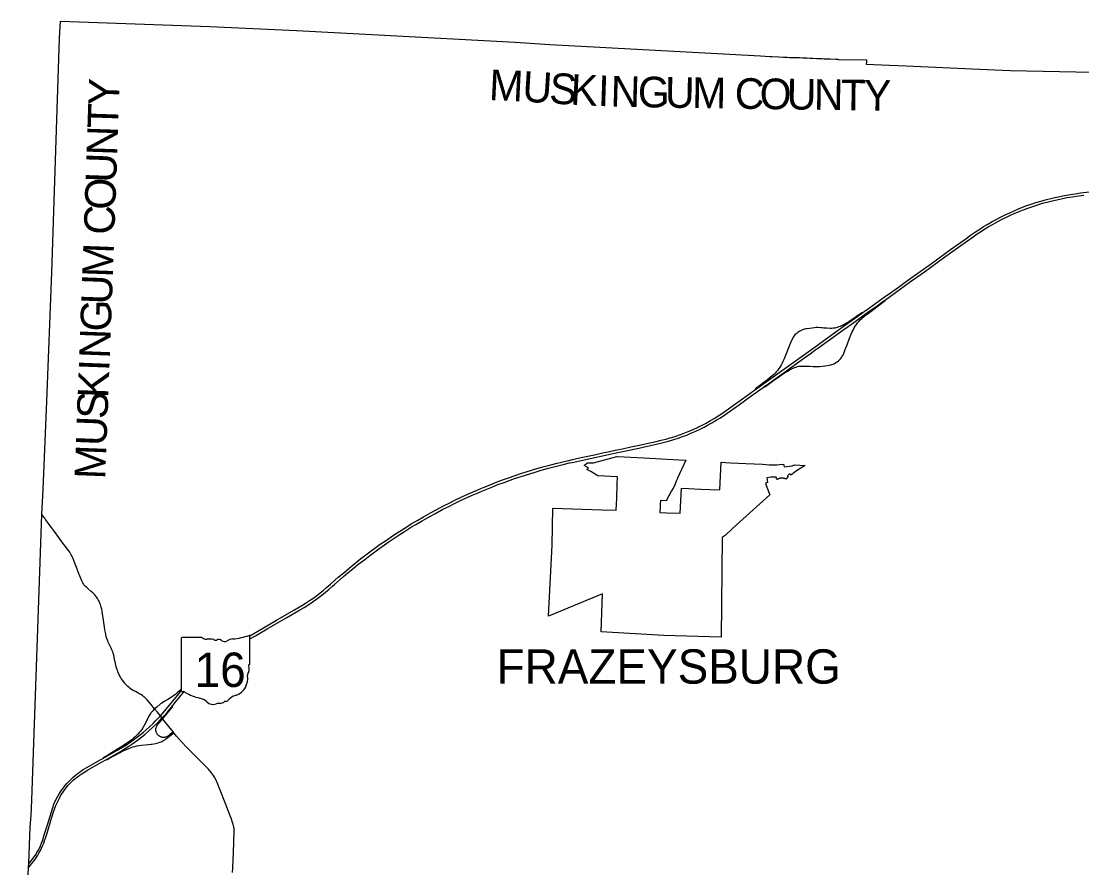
# Model space of a CAD drawing. Extents: x 2015843 to 2287843, y 623733 to 799733.
# Drawn here: x 2069607 to 2104221, y 756520 to 784141 of the extents above; entities that cross this region are included whole.
import ezdxf

# ---------------------------------------------------------------- set-up
doc = ezdxf.new("R2010")
doc.units = 0
for name, color, linetype in [('GM_X_Corporation', 7, 'Continuous'), ('GM_X_Corporation_Text', 7, 'Continuous'), ('GM_X_County', 7, 'Continuous'), ('GM_X_County_Text', 7, 'Continuous'), ('GM_X_State_Location', 7, 'Continuous'), ('GM_X_State_Route', 7, 'Continuous'), ('GM_X_State_Shield', 7, 'Continuous'), ('UT_P_Electric', 7, 'Continuous')]:
    doc.layers.add(name, color=color, linetype=linetype)

msp = doc.modelspace()

# ---------------------------------------------------------------- linework, layer by layer
at = {"layer": 'GM_X_Corporation'}
msp.add_lwpolyline([(2090451, 768115), (2090675, 768106), (2091108, 768088), (2091160, 768909), (2091385, 768898), (2091790, 768878), (2092405, 768847), (2092449, 769752), (2092753, 769737), (2093255, 769712), (2093802, 769685), (2094019, 769672), (2094081, 769669), (2094163, 769666), (2094214, 769665), (2094272, 769668), (2094356, 769677), (2094485, 769685), (2094507, 769605), (2094764, 769634), (2094846, 769670), (2095194, 769643), (2095191, 769641), (2095189, 769640), (2095187, 769639), (2095184, 769637), (2095180, 769635), (2095177, 769633), (2095173, 769631), (2095169, 769629), (2095166, 769627), (2095162, 769625), (2095159, 769624), (2095155, 769622), (2095152, 769620), (2095148, 769618), (2095145, 769616), (2095142, 769614), (2095138, 769612), (2095135, 769610), (2095131, 769608), (2095128, 769606), (2095124, 769604), (2095121, 769602), (2095120, 769601), (2095117, 769600), (2095114, 769598), (2095110, 769596), (2095107, 769594), (2095103, 769592), (2095100, 769590), (2095096, 769588), (2095093, 769586), (2095090, 769584), (2095086, 769582), (2095083, 769580), (2095079, 769578), (2095076, 769576), (2095072, 769574), (2095069, 769572), (2095065, 769570), (2095062, 769568), (2095059, 769565), (2095055, 769563), (2095052, 769561), (2095048, 769559), (2095045, 769557), (2095042, 769555), (2095038, 769553), (2095035, 769551), (2095031, 769549), (2095028, 769547), (2095025, 769544), (2095021, 769542), (2095018, 769540), (2095014, 769538), (2095011, 769536), (2095008, 769534), (2095004, 769532), (2095000, 769529), (2094996, 769527), (2094993, 769525), (2094990, 769523), (2094986, 769520), (2094983, 769518), (2094979, 769516), (2094976, 769514), (2094973, 769512), (2094969, 769510), (2094966, 769508), (2094963, 769505), (2094959, 769503), (2094956, 769501), (2094953, 769499), (2094949, 769497), (2094946, 769495), (2094942, 769492), (2094939, 769490), (2094936, 769488), (2094932, 769486), (2094929, 769484), (2094926, 769481), (2094923, 769479), (2094919, 769477), (2094916, 769475), (2094913, 769472), (2094909, 769470), (2094906, 769468), (2094903, 769466), (2094899, 769463), (2094896, 769461), (2094893, 769459), (2094890, 769456), (2094886, 769454), (2094883, 769452), (2094880, 769449), (2094877, 769447), (2094873, 769445), (2094870, 769443), (2094867, 769440), (2094864, 769438), (2094860, 769435), (2094857, 769433), (2094854, 769431), (2094851, 769428), (2094848, 769426), (2094844, 769424), (2094841, 769421), (2094838, 769419), (2094835, 769416), (2094832, 769414), (2094828, 769412), (2094825, 769409), (2094822, 769407), (2094819, 769404), (2094816, 769402), (2094813, 769399), (2094809, 769397), (2094806, 769394), (2094803, 769392), (2094800, 769389), (2094797, 769387), (2094794, 769384), (2094791, 769382), (2094787, 769379), (2094784, 769377), (2094781, 769374), (2094778, 769372), (2094775, 769369), (2094772, 769367), (2094769, 769364), (2094766, 769362), (2094763, 769359), (2094760, 769357), (2094757, 769354), (2094753, 769352), (2094750, 769349), (2094747, 769346), (2094744, 769344), (2094741, 769341), (2094738, 769339), (2094735, 769336), (2094731, 769333), (2094687, 769377), (2094612, 769312), (2094639, 769281), (2094562, 769203), (2094558, 769205), (2094555, 769207), (2094551, 769208), (2094548, 769210), (2094544, 769212), (2094540, 769213), (2094536, 769214), (2094533, 769216), (2094529, 769217), (2094525, 769218), (2094521, 769220), (2094517, 769221), (2094514, 769222), (2094510, 769223), (2094506, 769224), (2094502, 769225), (2094498, 769226), (2094494, 769226), (2094490, 769227), (2094486, 769228), (2094482, 769229), (2094478, 769229), (2094474, 769230), (2094470, 769230), (2094466, 769231), (2094462, 769231), (2094458, 769231), (2094454, 769232), (2094450, 769232), (2094446, 769232), (2094442, 769232), (2094438, 769232), (2094434, 769232), (2094431, 769232), (2094427, 769232), (2094423, 769232), (2094419, 769232), (2094415, 769232), (2094411, 769231), (2094407, 769231), (2094403, 769231), (2094399, 769230), (2094395, 769230), (2094391, 769229), (2094387, 769228), (2094383, 769228), (2094379, 769227), (2094375, 769226), (2094371, 769225), (2094367, 769224), (2094363, 769223), (2094359, 769222), (2094356, 769221), (2094352, 769220), (2094348, 769219), (2094344, 769218), (2094340, 769216), (2094337, 769215), (2094333, 769214), (2094329, 769212), (2094327, 769212), (2094325, 769211), (2094322, 769209), (2094315, 769207), (2094312, 769205), (2094308, 769203), (2094305, 769201), (2094301, 769199), (2094298, 769198), (2094294, 769196), (2094290, 769194), (2094287, 769192), (2094283, 769191), (2094279, 769189), (2094276, 769187), (2094272, 769186), (2094269, 769184), (2094268, 769184), (2094248, 769267), (2094074, 769267), (2093939, 769244), (2093962, 769085), (2093903, 769072), (2093907, 769031), (2093944, 768940), (2094043, 768692), (2093935, 768594), (2092835, 767601), (2092580, 767365), (2092479, 767294), (2092479, 767294), (2092455, 764039), (2090584, 764096), (2088537, 764215), (2088582, 765461), (2086820, 764727), (2086932, 767051), (2086954, 768249), (2088555, 768201), (2089023, 768183), (2089041, 768582), (2089061, 769039), (2089071, 769274), (2088428, 769311), (2088198, 769446), (2088072, 769514), (2088123, 769568), (2088052, 769606), (2087981, 769644), (2087976, 769648), (2088069, 769725), (2088076, 769726), (2088082, 769728), (2088281, 769735), (2089051, 769936), (2089070, 769940), (2089924, 769893), (2090119, 769882), (2091265, 769819), (2091293, 769818), (2091027, 769228), (2091023, 769218), (2090987, 769133), (2090947, 769039), (2090920, 768978), (2090916, 768968), (2090914, 768965), (2090913, 768961), (2090911, 768958), (2090911, 768956), (2090909, 768952), (2090907, 768948), (2090906, 768945), (2090904, 768942), (2090902, 768938), (2090900, 768935), (2090898, 768930), (2090896, 768927), (2090895, 768924), (2090893, 768921), (2090890, 768916), (2090888, 768912), (2090886, 768908), (2090882, 768903), (2090832, 768814), (2090769, 768701), (2090768, 768700), (2090761, 768687), (2090758, 768684), (2090755, 768678), (2090752, 768673), (2090749, 768669), (2090746, 768664), (2090743, 768659), (2090741, 768655), (2090739, 768652), (2090738, 768650), (2090733, 768642), (2090729, 768636), (2090726, 768631), (2090723, 768625), (2090720, 768620), (2090718, 768615), (2090715, 768611), (2090713, 768606), (2090711, 768601), (2090708, 768596), (2090705, 768591), (2090703, 768587), (2090701, 768582), (2090699, 768578), (2090696, 768572), (2090694, 768567), (2090692, 768562), (2090689, 768557), (2090687, 768553), (2090685, 768547), (2090682, 768540), (2090680, 768535), (2090678, 768531), (2090676, 768526), (2090671, 768514), (2090670, 768510), (2090668, 768506), (2090667, 768503), (2090665, 768498), (2090665, 768496), (2090664, 768494), (2090663, 768491), (2090467, 768500), (2090461, 768368), (2090459, 768300)], close=True, dxfattribs=at)
at = {"layer": 'GM_X_County'}
msp.add_lwpolyline([(2069607, 750462), (2069850, 756543), (2069853, 756656), (2069894, 757841), (2069935, 758229), (2069959, 758723), (2070278, 768051), (2070323, 768867), (2070448, 771746), (2070609, 775946), (2070855, 783589), (2070892, 784141), (2075761, 783968), (2078590, 783843), (2081257, 783694), (2085728, 783453), (2086861, 783383), (2088289, 783309), (2093740, 783008), (2094035, 782985), (2094106, 782985), (2094337, 782976), (2094488, 782969), (2094603, 782966), (2094685, 782962), (2094750, 782959), (2094881, 782955), (2095012, 782953), (2095111, 782950), (2095242, 782945), (2095356, 782939), (2095438, 782934), (2095573, 782928), (2095747, 782920), (2095812, 782918), (2095815, 782918), (2095910, 782915), (2096008, 782912), (2096189, 782906), (2096240, 782904), (2096257, 782902), (2096267, 782900), (2096273, 782897), (2097198, 782879), (2097195, 782802), (2097194, 782787), (2097189, 782758), (2097184, 782735), (2097949, 782707), (2098487, 782682), (2100643, 782587), (2101884, 782528), (2105109, 782463)], dxfattribs=at)
at = {"layer": 'GM_X_State_Route'}
for points in [[(2072992, 762537), (2072988, 762542), (2072947, 762593), (2072908, 762646), (2072874, 762699), (2072838, 762762), (2072809, 762816), (2072775, 762890), (2072756, 762935), (2072739, 762982), (2072719, 763044), (2072698, 763123), (2072683, 763187), (2072674, 763235), (2072667, 763267), (2072645, 763379), (2072626, 763458), (2072608, 763521), (2072592, 763566), (2072567, 763627), (2072540, 763685), (2072496, 763773), (2072475, 763818), (2072449, 763878), (2072431, 763923), (2072404, 764001), (2072385, 764064), (2072370, 764127), (2072357, 764191), (2072340, 764288), (2072324, 764379), (2072302, 764522), (2072279, 764680), (2072261, 764794), (2072246, 764891), (2072234, 764955), (2072219, 765019), (2072206, 765066), (2072190, 765112), (2072173, 765157), (2072146, 765216), (2072124, 765260), (2072099, 765302), (2072072, 765343), (2072043, 765382), (2072010, 765420), (2071977, 765456), (2071942, 765489), (2071893, 765532), (2071794, 765616), (2071745, 765660), (2071710, 765695), (2071688, 765718), (2071664, 765746), (2071643, 765779), (2071621, 765816), (2071588, 765884), (2071481, 766145), (2071424, 766297), (2071394, 766374), (2071328, 766541), (2071290, 766631), (2071269, 766676), (2071240, 766733), (2071215, 766776), (2071189, 766817), (2071123, 766910), (2070938, 767159), (2070840, 767291), (2070694, 767488), (2070597, 767620), (2070518, 767725), (2070440, 767830), (2070401, 767883), (2070373, 767922), (2070354, 767948), (2070324, 767987), (2070279, 768048)], [(2074244, 761355), (2074225, 761379), (2074206, 761404), (2074164, 761456), (2074148, 761476), (2074051, 761597), (2073958, 761710), (2073833, 761861), (2073716, 761998), (2073673, 762043), (2073640, 762075), (2073607, 762102), (2073562, 762136), (2073509, 762170), (2073444, 762207), (2073332, 762266), (2073260, 762306), (2073206, 762339), (2073166, 762368), (2073126, 762398), (2073091, 762429), (2073052, 762466), (2073021, 762502), (2072992, 762537)], [(2075142, 760317), (2075100, 760359), (2075076, 760383), (2074996, 760465), (2074872, 760594), (2074762, 760716), (2074679, 760812), (2074587, 760925), (2074564, 760953), (2074530, 760994), (2074469, 761070), (2074378, 761186), (2074266, 761328), (2074244, 761355)], [(2076532, 756984), (2076548, 757385), (2076557, 757677), (2076558, 757728), (2076555, 757779), (2076552, 757814), (2076548, 757845), (2076539, 757892), (2076527, 757940), (2076507, 758002), (2076469, 758110), (2076352, 758413), (2076303, 758535), (2076058, 759159), (2076022, 759250), (2075990, 759326), (2075955, 759399), (2075916, 759471), (2075883, 759528), (2075854, 759569), (2075815, 759620), (2075777, 759667), (2075751, 759698), (2075720, 759733), (2075284, 760174), (2075239, 760220), (2075146, 760313), (2075142, 760317)], [(2076507, 756363), (2076513, 756522), (2076524, 756801), (2076532, 756984)]]:
    msp.add_lwpolyline(points, dxfattribs=at)
at = {"layer": 'GM_X_State_Shield'}
for p, q in [((2074829, 764001), (2074829, 762300)), ((2075507, 764030), (2074851, 764030)), ((2077070, 763183), (2077070, 764073)), ((2077070, 763183), (2077070, 763183))]:
    msp.add_line(p, q, dxfattribs=at)
for centre, radius, start, end in [((2074855, 764005), 26, 98.1301, 188.1301), ((2075664, 764228), 252, 231.6195, 271.1119), ((2075747, 763075), 904, 80.4867, 94.9883), ((2075953, 764014), 72.7, 219.7921, 297.1024), ((2076059, 763817), 151, 54.4667, 119.1411), ((2076254, 764087), 182, 233.8562, 294.8282), ((2076575, 763511), 478, 97.3462, 120.7689), ((2076272, 766350), 2377, 275.8445, 288.9065), ((2077046, 764076), 25, 351.8621, 97.738), ((2077160, 762810), 169, 136.8065, 186.9296), ((2077065, 763117), 38.6, 107.944, 210.337), ((2076819, 763005), 232, 340.033, 23.6496), ((2077044, 763179), 26.7, 289.6038, 7.7341), ((2076405, 762697), 595, 292.3089, 8.9858), ((2074855, 762296), 26.2, 171.9584, 258.3066), ((2074859, 762470), 200, 267.339, 280.6039), ((2074900, 762202), 72.1, 29.7484, 93.2717), ((2075810, 763730), 1716, 240.4129, 257.1985), ((2075298, 761536), 537, 47.1842, 75.836), ((2075879, 762193), 341, 230.7004, 286.2918), ((2076076, 761605), 280, 85.6951, 111.2099), ((2076101, 762066), 182, 268.777, 315.5493), ((2076265, 761901), 51.1, 65.7517, 132.6484), ((2076243, 762135), 192, 282.8732, 323.2771), ((2076656, 761822), 326, 94.4031, 142.5768)]:
    msp.add_arc(centre, radius, start, end, dxfattribs=at)
at = {"layer": 'UT_P_Electric'}
msp.add_line((2097076, 774636), (2097196, 774722), dxfattribs=at)
for points in [[(2097196, 774722), (2097221, 774740), (2097502, 774940), (2097742, 775111), (2097982, 775283), (2098235, 775464), (2098462, 775627), (2098688, 775790), (2099315, 776239), (2099940, 776689), (2100261, 776917), (2100433, 777042), (2100594, 777156), (2100756, 777268), (2100892, 777359), (2101016, 777438), (2101156, 777523), (2101298, 777605), (2101427, 777675), (2101573, 777751), (2101720, 777823), (2101868, 777893), (2102018, 777959), (2102154, 778017), (2102291, 778071), (2102429, 778123), (2102599, 778182), (2102724, 778223), (2102928, 778285), (2102963, 778295), (2103070, 778325), (2103165, 778350), (2103340, 778392), (2103500, 778427), (2103661, 778459), (2103855, 778492), (2104001, 778514), (2104179, 778537), (2104571, 778580)], [(2097827, 775064), (2097929, 775136), (2098182, 775318), (2098420, 775491), (2098634, 775644), (2098834, 775787), (2099087, 775969), (2099500, 776265), (2099713, 776418), (2099940, 776579), (2100273, 776819), (2100459, 776953), (2100673, 777105), (2100808, 777199), (2100917, 777272), (2101027, 777343), (2101168, 777428), (2101324, 777518), (2101482, 777605), (2101627, 777681), (2101759, 777747), (2101878, 777803), (2102013, 777863), (2102195, 777939), (2102316, 777987), (2102455, 778039), (2102625, 778099), (2102781, 778151), (2102937, 778200), (2103022, 778224), (2103079, 778241), (2103206, 778274), (2103350, 778307), (2103607, 778361), (2103736, 778385), (2103914, 778414), (2104109, 778441), (2104289, 778463)], [(2095568, 772870), (2095643, 772870), (2095675, 772872), (2095919, 772906), (2095984, 772917), (2096032, 772928), (2096064, 772938), (2096110, 772955), (2096154, 772976), (2096197, 773001), (2096238, 773029), (2096276, 773060), (2096312, 773094), (2096345, 773130), (2096375, 773169), (2096394, 773196), (2096419, 773239), (2096442, 773283), (2096462, 773328), (2096503, 773435), (2096573, 773620), (2096644, 773804), (2096693, 773926), (2096726, 774001), (2096755, 774060), (2096795, 774132), (2096829, 774188), (2096866, 774243), (2096905, 774296), (2096947, 774346), (2096991, 774395), (2097038, 774441), (2097086, 774485), (2097150, 774538), (2097214, 774588), (2097476, 774781), (2097716, 774958), (2097753, 774985), (2097803, 775026), (2097815, 775040), (2097827, 775064)], [(2097287, 774680), (2097541, 774860), (2097728, 774994), (2097827, 775064)], [(2079771, 765710), (2079830, 765761), (2079933, 765851), (2080129, 766024), (2080279, 766152), (2080431, 766278), (2080597, 766411), (2080817, 766583), (2080986, 766712), (2081144, 766830), (2081277, 766926), (2081465, 767059), (2081613, 767161), (2081940, 767379), (2082119, 767495), (2082314, 767617), (2082482, 767719), (2082695, 767843), (2082923, 767973), (2083124, 768083), (2083370, 768215), (2083560, 768312), (2083765, 768415), (2083943, 768500), (2084300, 768664), (2084466, 768736), (2084639, 768809), (2084753, 768856), (2084966, 768943), (2085164, 769020), (2085364, 769095), (2085564, 769168), (2085704, 769217), (2086062, 769334), (2086376, 769432), (2086580, 769492), (2086817, 769558), (2086992, 769603), (2087294, 769679), (2087502, 769728), (2087585, 769746), (2087742, 769780), (2088079, 769853), (2088575, 769961), (2088816, 770012), (2089024, 770057), (2089393, 770136), (2089762, 770215), (2090291, 770330), (2090514, 770381), (2090642, 770414), (2090736, 770440), (2090909, 770492), (2091049, 770537), (2091188, 770586), (2091326, 770639), (2091463, 770695), (2091628, 770767), (2091648, 770777), (2091746, 770823), (2091893, 770896), (2092009, 770957), (2092152, 771037), (2092293, 771120), (2092405, 771189), (2092528, 771270), (2092649, 771355), (2092863, 771507), (2093050, 771640), (2093210, 771755), (2093463, 771936), (2093530, 771984), (2093717, 772117), (2093820, 772191), (2093837, 772203), (2094036, 772347), (2094169, 772443), (2094275, 772520), (2094583, 772738), (2094677, 772805), (2094823, 772910), (2095222, 773198), (2095343, 773283), (2095410, 773331), (2095556, 773436), (2095591, 773461), (2096421, 774059), (2096595, 774183), (2096781, 774316), (2096912, 774411), (2097034, 774499), (2097287, 774680)], [(2077067, 764090), (2077517, 764351), (2077941, 764600), (2078509, 764929), (2078764, 765078), (2078890, 765155), (2079014, 765235), (2079122, 765309), (2079242, 765396), (2079359, 765486), (2079462, 765568), (2079574, 765664), (2079696, 765770), (2079723, 765793), (2079956, 765999), (2080131, 766148), (2080307, 766296), (2080497, 766451), (2080638, 766564), (2080859, 766734), (2081029, 766862), (2081188, 766978), (2081322, 767073), (2081524, 767213), (2081755, 767369), (2081961, 767503), (2082155, 767625), (2082336, 767737), (2082548, 767862), (2082732, 767969), (2082961, 768097), (2083148, 768199), (2083366, 768313), (2083570, 768418), (2083717, 768491), (2084014, 768631), (2084208, 768718), (2084508, 768850), (2084605, 768891), (2084719, 768939), (2084917, 769019), (2085146, 769109), (2085345, 769184), (2085515, 769245), (2085731, 769321), (2085918, 769382), (2086263, 769490), (2086435, 769542), (2086672, 769610), (2086893, 769671), (2087100, 769724), (2087195, 769747), (2087371, 769789), (2087476, 769812), (2087594, 769839), (2087883, 769901), (2088315, 769995), (2088491, 770034), (2088635, 770066), (2088763, 770093), (2088988, 770141), (2089228, 770192), (2089501, 770250), (2089886, 770334), (2090126, 770385), (2090287, 770419), (2090447, 770456), (2090542, 770479), (2090653, 770509), (2090779, 770545), (2090843, 770561), (2090906, 770579), (2090985, 770603), (2091062, 770630), (2091154, 770665), (2091373, 770750), (2091456, 770787), (2091539, 770823), (2091680, 770889), (2091710, 770903), (2091784, 770938), (2091872, 770983), (2091959, 771030), (2092102, 771110), (2092243, 771193), (2092355, 771263), (2092464, 771335), (2092612, 771438), (2092812, 771582), (2093145, 771821), (2093505, 772079), (2093544, 772107), (2093772, 772271), (2095595, 773575), (2095849, 773756), (2096195, 774005), (2096435, 774176), (2096622, 774309), (2096836, 774462), (2096913, 774518), (2097076, 774636)], [(2097076, 774636), (2097040, 774625), (2097011, 774609), (2096964, 774575), (2096913, 774539), (2096779, 774445), (2096690, 774382), (2096621, 774337), (2096551, 774295), (2096480, 774255), (2096406, 774218), (2096383, 774207)], [(2095622, 774145), (2095572, 774145), (2095549, 774145), (2095498, 774140), (2095422, 774131), (2095259, 774109), (2095210, 774101), (2095161, 774090), (2095114, 774075), (2095083, 774063), (2095038, 774041), (2094995, 774016), (2094954, 773987), (2094929, 773967), (2094897, 773940), (2094861, 773905)], [(2096383, 774207), (2096332, 774184), (2096286, 774165), (2096239, 774149), (2096192, 774137), (2096160, 774130), (2096111, 774123), (2096062, 774120), (2096013, 774120), (2095898, 774125), (2095803, 774128), (2095747, 774132), (2095703, 774137), (2095622, 774145)], [(2094861, 773905), (2094828, 773869), (2094789, 773813), (2094764, 773765), (2094718, 773646), (2094507, 773130), (2094468, 773040), (2094439, 772981), (2094407, 772923), (2094373, 772867), (2094337, 772813), (2094298, 772760), (2094256, 772709), (2094212, 772661), (2094166, 772614), (2094118, 772569), (2094056, 772516), (2093966, 772445), (2093809, 772326), (2093785, 772308), (2093612, 772178), (2093576, 772150), (2093557, 772128), (2093544, 772107)], [(2093820, 772191), (2093876, 772212), (2093913, 772234), (2094173, 772427), (2094287, 772506), (2094420, 772600), (2094503, 772654), (2094601, 772714), (2094686, 772762), (2094759, 772800), (2094769, 772805)], [(2094769, 772805), (2094803, 772822), (2094848, 772841), (2094895, 772857), (2094942, 772871), (2094990, 772881), (2095038, 772888), (2095087, 772891), (2095153, 772891), (2095349, 772883), (2095449, 772879), (2095568, 772870)], [(2077070, 763986), (2077253, 764092), (2077636, 764314), (2078274, 764685), (2078671, 764917), (2078840, 765017), (2078994, 765112), (2079103, 765184), (2079211, 765259), (2079330, 765346), (2079421, 765415), (2079536, 765508), (2079661, 765613), (2079771, 765710)], [(2069854, 756653), (2069925, 756732), (2069976, 756797), (2070024, 756863), (2070079, 756945), (2070122, 757015), (2070162, 757086), (2070199, 757160), (2070233, 757235), (2070270, 757326), (2070308, 757434), (2070359, 757590), (2070461, 757920), (2070549, 758205), (2070591, 758343), (2070638, 758483), (2070677, 758590), (2070708, 758666), (2070735, 758726), (2070763, 758785), (2070802, 758857), (2070843, 758927), (2070887, 758996), (2070933, 759064), (2070982, 759130), (2071033, 759194), (2071097, 759268), (2071164, 759340), (2071233, 759410), (2071293, 759466), (2071367, 759530), (2071430, 759582), (2071496, 759631), (2071549, 759668), (2071632, 759721), (2071745, 759789), (2072186, 760040), (2072269, 760087), (2072786, 760380), (2072913, 760455), (2073038, 760534), (2073161, 760615), (2073282, 760700), (2073401, 760788), (2073505, 760868), (2073594, 760942), (2073693, 761028), (2073790, 761116), (2073909, 761229), (2073991, 761309), (2074082, 761404), (2074148, 761476), (2074160, 761489), (2074235, 761575), (2074342, 761700), (2074705, 762144), (2074829, 762294)], [(2074829, 762343), (2074775, 762292), (2074701, 762227), (2074638, 762175), (2074586, 762136), (2074532, 762098), (2074477, 762063), (2074392, 762014), (2074292, 761957), (2074237, 761923), (2074196, 761896), (2074156, 761867), (2074028, 761765), (2073958, 761710)], [(2074191, 761388), (2074206, 761404), (2074274, 761479), (2074370, 761591), (2074557, 761818), (2074631, 761907), (2074789, 762096), (2074930, 762267)], [(2073958, 761710), (2073891, 761634), (2073868, 761606), (2073851, 761583), (2073835, 761562), (2073808, 761521), (2073777, 761464), (2073671, 761261), (2073616, 761160), (2073575, 761090), (2073539, 761035), (2073501, 760981), (2073461, 760930), (2073418, 760881), (2073373, 760833), (2073326, 760788), (2073277, 760745), (2073213, 760694), (2073120, 760626), (2073026, 760561), (2072916, 760490), (2072749, 760387), (2072434, 760191), (2072357, 760149), (2072296, 760113), (2072269, 760087)], [(2074564, 760953), (2074488, 760887), (2074451, 760854), (2074412, 760825), (2074385, 760807), (2074355, 760792), (2074340, 760786), (2074324, 760781), (2074309, 760777), (2074292, 760774), (2074276, 760772), (2074260, 760772), (2074243, 760772), (2074227, 760773), (2074211, 760776), (2074195, 760779), (2074179, 760784), (2074164, 760789), (2074148, 760796), (2074134, 760803), (2074120, 760811), (2074106, 760821), (2074093, 760831), (2074081, 760842), (2074069, 760853), (2074059, 760866), (2074049, 760879), (2074040, 760893), (2074032, 760907), (2074024, 760922), (2074013, 760952), (2074009, 760968), (2074003, 761001), (2074002, 761017), (2074003, 761050), (2074005, 761066), (2074013, 761098), (2074018, 761113), (2074031, 761143), (2074047, 761172), (2074065, 761199), (2074096, 761238), (2074128, 761275), (2074207, 761358), (2074225, 761379), (2074262, 761420), (2074317, 761487), (2074500, 761712), (2074520, 761738), (2074542, 761771), (2074550, 761789), (2074557, 761818)], [(2071262, 759334), (2071306, 759375), (2071368, 759430), (2071432, 759481), (2071497, 759530), (2071565, 759577), (2071648, 759630), (2071775, 759706), (2072131, 759910), (2072371, 760047), (2072601, 760177), (2072843, 760316), (2072999, 760407), (2073124, 760485), (2073219, 760549), (2073327, 760624), (2073445, 760712), (2073549, 760792), (2073637, 760865), (2073760, 760973), (2073894, 761094), (2074001, 761196), (2074117, 761311), (2074191, 761388)], [(2073852, 760548), (2073873, 760551), (2073938, 760560), (2073987, 760570), (2074035, 760582), (2074082, 760596), (2074128, 760613), (2074174, 760632), (2074233, 760661), (2074290, 760694), (2074331, 760722), (2074396, 760771), (2074499, 760854), (2074587, 760925)], [(2072371, 760047), (2072411, 760056), (2072469, 760088), (2072677, 760199), (2072832, 760281), (2072935, 760333), (2073039, 760381), (2073115, 760413), (2073176, 760437), (2073255, 760462), (2073318, 760480), (2073382, 760494), (2073447, 760506), (2073529, 760517), (2073758, 760538), (2073852, 760548)], [(2070383, 757444), (2070385, 757448), (2070431, 757588), (2070509, 757839), (2070600, 758137), (2070621, 758203), (2070654, 758309), (2070696, 758434), (2070730, 758526), (2070768, 758617), (2070809, 758707), (2070853, 758795), (2070894, 758866), (2070936, 758936), (2070982, 759005), (2071030, 759071), (2071080, 759136), (2071133, 759199), (2071188, 759260), (2071246, 759319), (2071262, 759334)], [(2069851, 756540), (2069998, 756713), (2070047, 756779), (2070093, 756846), (2070146, 756929), (2070187, 757000), (2070234, 757086), (2070270, 757159), (2070303, 757234), (2070340, 757325), (2070383, 757444)]]:
    msp.add_lwpolyline(points, dxfattribs=at)

# ---------------------------------------------------------------- texts
at = {"layer": 'GM_X_Corporation_Text'}
msp.add_text('FRAZEYSBURG', height=1120, rotation=0, dxfattribs=at).set_placement((2085123, 762527))
at = {"layer": 'GM_X_County_Text'}
for s, rotation, p in [('M', 357.2115, (2084860, 781572)), ('U', 356.4278, (2085942, 781520)), ('S', 356.4112, (2086824, 781464)), ('K', 357.0853, (2087513, 781421)), ('I', 358.1377, (2088417, 781376)), ('N', 358.4214, (2088831, 781362)), ('G', 358.9475, (2089725, 781338)), ('U', 359.1434, (2090613, 781321)), ('M', 359.1871, (2091498, 781308)), ('C', 359.1883, (2092889, 781288)), ('O', 359.1883, (2093702, 781277)), ('Y', 88.0873, (2072791, 781371)), ('U', 359.1877, (2094587, 781264)), ('N', 359.1883, (2095471, 781252)), ('T', 359.1887, (2096355, 781239)), ('Y', 359.1883, (2097103, 781229)), ('T', 88.0873, (2072766, 780625)), ('N', 88.0714, (2072736, 779743)), ('U', 88.0411, (2072706, 778860)), ('O', 88.001, (2072675, 777977)), ('C', 87.9537, (2072646, 777162)), ('M', 87.9381, (2072596, 775770)), ('U', 87.8907, (2072564, 774887)), ('G', 87.85, (2072530, 774004)), ('N', 87.8204, (2072497, 773122)), ('I', 87.807, (2072481, 772715)), ('K', 87.7997, (2072447, 771832)), ('S', 87.7976, (2072421, 771153)), ('U', 87.7975, (2072387, 770271)), ('M', 87.7975, (2072346, 769185))]:
    msp.add_text(s, height=1000, rotation=rotation, dxfattribs=at).set_placement(p)
at = {"layer": 'GM_X_State_Location'}
for s, p in [('s', (2098460, 775397)), ('r', (2098460, 775397)), ('s', (2075589, 762857)), ('r', (2075589, 762857)), ('s', (2076332, 758527)), ('r', (2076332, 758527))]:
    msp.add_text(s, height=1, dxfattribs=at).set_placement(p)
for s, p in [('16', (2098208, 775324)), ('16', (2075337, 762784)), ('586', (2075979, 758454))]:
    msp.add_text(s, height=1, rotation=0, dxfattribs=at).set_placement(p)
at = {"layer": 'GM_X_State_Shield'}
msp.add_text('16', height=1120.7, dxfattribs=at).set_placement((2075267, 762420))

doc.saveas('drawing.dxf')
